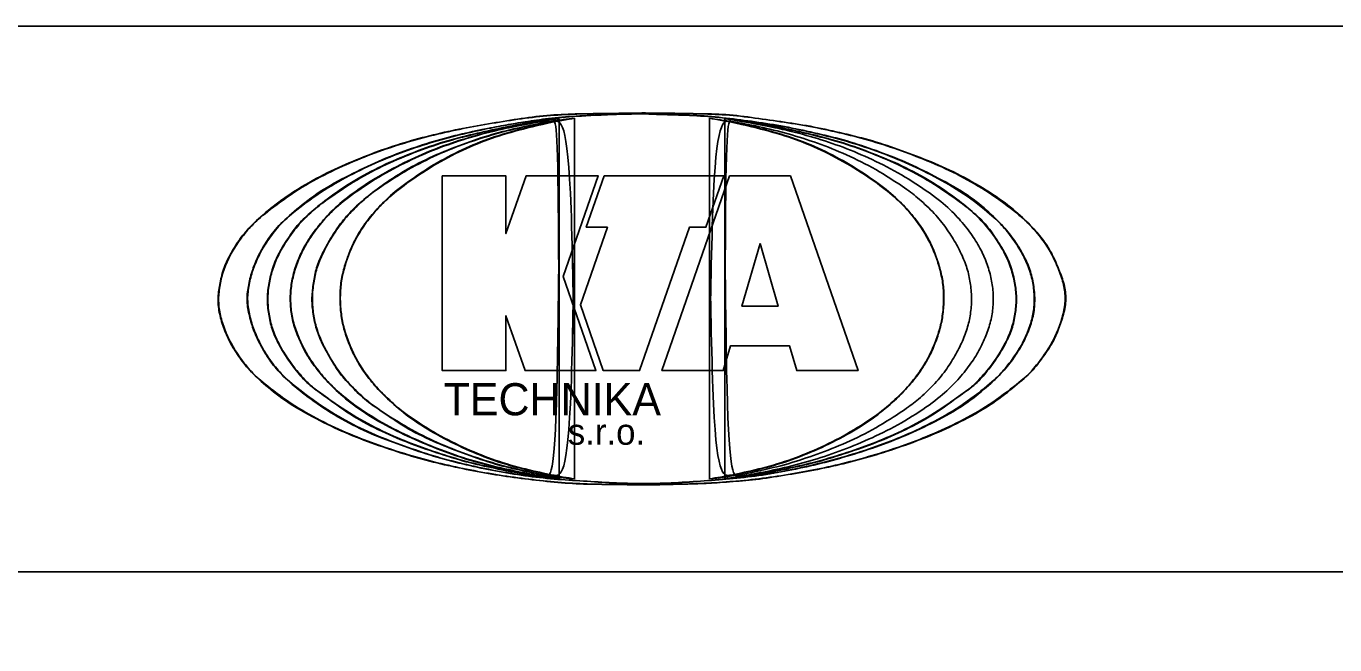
# Model space of a CAD drawing. Extents: x 25 to 46, y -50 to -20.3.
# Drawn here: x 37.705 to 42.505, y -37.068 to -34.8 of the extents above; entities that cross this region are included whole.
import ezdxf

# ---------------------------------------------------------------- set-up
doc = ezdxf.new("R2010")
doc.units = 0
doc.layers.add('_popis', color=7, linetype='Continuous')
doc.layers.add('Rozpiska_pole_6', color=7, linetype='Continuous')

msp = doc.modelspace()

# ---------------------------------------------------------------- linework, layer by layer
at = {"layer": '_popis'}
for p, q in [((40.2681, -35.1392), (40.2677, -36.458)), ((39.2313, -35.3488), (39.2313, -36.0628)), ((39.465, -35.3488), (39.2313, -35.3488)), ((39.5386, -35.3488), (39.465, -35.5605)), ((39.465, -35.5605), (39.465, -35.3488)), ((39.8036, -35.3488), (39.5386, -35.3488)), ((39.675, -35.7182), (39.8036, -35.3488)), ((39.825, -35.3488), (39.7594, -35.5375)), ((40.2641, -35.3488), (39.825, -35.3488)), ((40.037, -36.0626), (40.2855, -35.3488)), ((40.1984, -35.5375), (40.2641, -35.3488)), ((40.2855, -35.3488), (40.3969, -35.3488)), ((40.3969, -35.3488), (40.5083, -35.3488)), ((40.5083, -35.3488), (40.7567, -36.0626)), ((39.8369, -35.5375), (39.7381, -35.8213)), ((39.7594, -35.5375), (39.8369, -35.5375)), ((39.9551, -36.0628), (40.1379, -35.5375)), ((40.1379, -35.5375), (40.1984, -35.5375)), ((40.3969, -35.5973), (40.3305, -35.8269)), ((40.4633, -35.8269), (40.3969, -35.5973)), ((39.795, -36.0628), (39.675, -35.7182)), ((39.7381, -35.8213), (39.8222, -36.0628)), ((40.3305, -35.8269), (40.3969, -35.8269)), ((40.3969, -35.8269), (40.4633, -35.8269)), ((39.465, -36.0628), (39.465, -35.8616)), ((39.465, -35.8616), (39.535, -36.0628)), ((40.2887, -35.9716), (40.2623, -36.0628)), ((40.3969, -35.9716), (40.2887, -35.9716)), ((40.5051, -35.9716), (40.3969, -35.9716)), ((40.5315, -36.0628), (40.5051, -35.9716)), ((39.2313, -36.0628), (39.465, -36.0628)), ((39.535, -36.0628), (39.795, -36.0628)), ((39.8222, -36.0628), (39.9551, -36.0628)), ((40.2623, -36.0628), (40.037, -36.0626)), ((40.7567, -36.0626), (40.5315, -36.0628))]:
    msp.add_line(p, q, dxfattribs=at)
for points in [[(39.2313, -35.3488), (39.2313, -36.0628), (39.465, -36.0628), (39.465, -35.8616), (39.535, -36.0628), (39.795, -36.0628), (39.675, -35.7182), (39.8036, -35.3488), (39.5386, -35.3488), (39.465, -35.5605), (39.465, -35.3488), (39.2313, -35.3488)], [(39.825, -35.3488), (39.7594, -35.5375), (39.8369, -35.5375), (39.7381, -35.8213), (39.8222, -36.0628), (39.9551, -36.0628), (40.1379, -35.5375), (40.1984, -35.5375), (40.2641, -35.3488), (39.825, -35.3488)], [(40.3969, -35.9716), (40.2887, -35.9716), (40.2623, -36.0628), (40.037, -36.0626), (40.2855, -35.3488), (40.3969, -35.3488)], [(40.3969, -35.9716), (40.5051, -35.9716), (40.5315, -36.0628), (40.7567, -36.0626), (40.5083, -35.3488), (40.3969, -35.3488)], [(40.3969, -35.8269), (40.3305, -35.8269), (40.3969, -35.5973)], [(40.3969, -35.8269), (40.4633, -35.8269), (40.3969, -35.5973)]]:
    msp.add_lwpolyline(points, dxfattribs=at)
for points, degree in [([(39.9639, -35.1182), (39.9235, -35.1188), (39.852, -35.1199), (39.7448, -35.1208), (39.642, -35.1242), (39.5347, -35.1357), (39.4277, -35.1537), (39.3201, -35.1713), (39.2128, -35.1946), (39.1051, -35.2223), (38.9975, -35.2573), (38.8906, -35.3005), (38.7817, -35.3493), (38.6736, -35.4136), (38.589, -35.4768), (38.5246, -35.5353), (38.4849, -35.5846), (38.452, -35.639), (38.4265, -35.6924), (38.4148, -35.7474), (38.4067, -35.8011), (38.4133, -35.8559), (38.4303, -35.9096), (38.4542, -35.9643), (38.4893, -36.0177), (38.5268, -36.0666), (38.5904, -36.1238), (38.6724, -36.1873), (38.7823, -36.2472), (38.8896, -36.2978), (38.9979, -36.3377), (39.1054, -36.3729), (39.2125, -36.4023), (39.3197, -36.4256), (39.427, -36.4454), (39.5348, -36.4603), (39.6419, -36.4721), (39.7493, -36.4805), (39.8565, -36.4792), (39.9639, -36.483), (40.0712, -36.4798), (40.1532, -36.4786), (40.1993, -36.4763), (40.2097, -36.4757)], 3), ([(39.9639, -35.1182), (39.8427, -35.1199), (39.7495, -35.1211), (39.6423, -35.1255), (39.5351, -35.1368), (39.4279, -35.1536), (39.3205, -35.1722), (39.2133, -35.1952), (39.1061, -35.2232), (38.9987, -35.2583), (38.8915, -35.3009), (38.7849, -35.3503), (38.6775, -35.4138), (38.5703, -35.4945), (38.5286, -35.5334), (38.4849, -35.5873), (38.4523, -35.6406), (38.4282, -35.6944), (38.4153, -35.7478), (38.4091, -35.8015), (38.4147, -35.8543), (38.431, -35.9085), (38.4551, -35.9623), (38.4888, -36.0156), (38.532, -36.0694), (38.5702, -36.1052), (38.6774, -36.1865), (38.7846, -36.2471), (38.8906, -36.2964), (38.9989, -36.3373), (39.1065, -36.3723), (39.2131, -36.4014), (39.3197, -36.425), (39.4275, -36.4446), (39.535, -36.4598), (39.6427, -36.4716), (39.7487, -36.4789), (39.8568, -36.4801), (39.9639, -36.4818), (40.0711, -36.4801), (40.1786, -36.4773), (40.2858, -36.4705), (40.3924, -36.4605), (40.4999, -36.4442), (40.6071, -36.4251), (40.7143, -36.401), (40.8218, -36.3713), (40.929, -36.336), (41.0362, -36.2945), (41.1428, -36.2446), (41.2508, -36.1813), (41.3585, -36.0978), (41.3905, -36.0692), (41.4326, -36.0159), (41.468, -35.9626), (41.4928, -35.9085), (41.5102, -35.8552), (41.5187, -35.8015), (41.5124, -35.748), (41.4939, -35.6942), (41.4698, -35.6394), (41.4378, -35.5872), (41.3924, -35.5334), (41.3593, -35.5009), (41.2509, -35.417), (41.1437, -35.3537), (41.0373, -35.3029), (40.9295, -35.2614), (40.8218, -35.2244), (40.7152, -35.1964), (40.6071, -35.1722), (40.4994, -35.1537), (40.3917, -35.1386), (40.2853, -35.125), (40.1784, -35.1211), (40.0713, -35.1192), (39.9639, -35.1182), (39.9639, -35.1182), (39.9639, -35.1182)], 3), ([(39.9639, -35.1211), (39.9997, -35.1226), (40.0713, -35.1255), (40.1787, -35.1265), (40.2858, -35.1383), (40.393, -35.1519), (40.5005, -35.1698), (40.6076, -35.1935), (40.7158, -35.2191), (40.8227, -35.2556), (40.9309, -35.2969), (41.0378, -35.3497), (41.1493, -35.4096), (41.2316, -35.4752), (41.2925, -35.5363), (41.331, -35.5848), (41.364, -35.639), (41.3885, -35.6928), (41.4013, -35.7476), (41.406, -35.8017), (41.4019, -35.8563), (41.3856, -35.9101), (41.3615, -35.9642), (41.3273, -36.0178), (41.2909, -36.0655), (41.2291, -36.1234), (41.1493, -36.1893), (41.0386, -36.2517), (40.9304, -36.3018), (40.8228, -36.3436), (40.715, -36.3773), (40.6078, -36.4072), (40.5001, -36.4295), (40.393, -36.4491), (40.2855, -36.4596), (40.1784, -36.4688), (40.0713, -36.4757), (39.9639, -36.4792), (39.8566, -36.4751), (39.7494, -36.4675), (39.6419, -36.4616), (39.5346, -36.4489), (39.4272, -36.4315), (39.3199, -36.4087), (39.2119, -36.3821), (39.1053, -36.3453), (38.9969, -36.3064), (38.8884, -36.2571), (38.7805, -36.1918), (38.696, -36.1276), (38.6313, -36.0686), (38.5928, -36.0182), (38.5608, -35.9637), (38.5367, -35.9099), (38.5218, -35.8558), (38.5123, -35.8015), (38.5206, -35.7471), (38.5345, -35.693), (38.5572, -35.6389), (38.589, -35.5849), (38.6276, -35.5322), (38.6946, -35.4726), (38.7792, -35.4054), (38.8901, -35.3461), (38.997, -35.2943), (39.1048, -35.2523), (39.2124, -35.218), (39.32, -35.1904), (39.4116, -35.1723), (39.4832, -35.1591), (39.5546, -35.1477), (39.6419, -35.1348), (39.7494, -35.1281), (39.8567, -35.1236), (39.9282, -35.122), (39.9639, -35.1211)], 3), ([(39.9639, -35.1211), (39.8567, -35.124), (39.7495, -35.1284), (39.6423, -35.1363), (39.5351, -35.1509), (39.4869, -35.1587), (39.428, -35.1694), (39.3205, -35.1913), (39.2133, -35.2188), (39.1059, -35.2532), (38.9988, -35.2952), (38.8914, -35.3463), (38.7848, -35.4063), (38.6775, -35.4883), (38.6298, -35.5333), (38.5888, -35.5872), (38.558, -35.6404), (38.5355, -35.6944), (38.5215, -35.7477), (38.5153, -35.8015), (38.5226, -35.8551), (38.5377, -35.9083), (38.5613, -35.9622), (38.5928, -36.0158), (38.6349, -36.0696), (38.6775, -36.11), (38.7847, -36.1919), (38.8914, -36.256), (38.9986, -36.3054), (39.1058, -36.3452), (39.2132, -36.3807), (39.3204, -36.4082), (39.4276, -36.4306), (39.535, -36.4482), (39.6422, -36.4605), (39.7494, -36.4678), (39.8567, -36.4745), (39.9639, -36.4779), (40.0711, -36.4751), (40.1786, -36.4684), (40.2852, -36.4594), (40.3924, -36.4476), (40.4999, -36.4291), (40.607, -36.4061), (40.7142, -36.3769), (40.8217, -36.3426), (40.9289, -36.3011), (41.0361, -36.2512), (41.1435, -36.1886), (41.2507, -36.1028), (41.285, -36.0695), (41.3277, -36.0156), (41.3608, -35.9624), (41.3849, -35.9085), (41.4, -35.8553), (41.4045, -35.802), (41.4, -35.7479), (41.3871, -35.6947), (41.3636, -35.6408), (41.331, -35.5872), (41.2883, -35.5333), (41.2507, -35.4952), (41.1436, -35.4105), (41.0362, -35.3496), (40.929, -35.298), (40.8218, -35.256), (40.7144, -35.2206), (40.6073, -35.1937), (40.5001, -35.1707), (40.3926, -35.1526), (40.2855, -35.1385), (40.1786, -35.1283), (40.0714, -35.1249), (39.9639, -35.1211), (39.9639, -35.1211), (39.9639, -35.1211)], 3), ([(39.7161, -36.4596), (39.6914, -36.4575), (39.6304, -36.4523), (39.5347, -36.4318), (39.4265, -36.4074), (39.3198, -36.3704), (39.2116, -36.3288), (39.1018, -36.2769), (39.021, -36.2196), (38.9493, -36.1723), (38.9019, -36.1253), (38.8532, -36.0728), (38.8201, -36.0165), (38.7893, -35.964), (38.7686, -35.9101), (38.7572, -35.8559), (38.7513, -35.8017), (38.7578, -35.7476), (38.7662, -35.6929), (38.7884, -35.6393), (38.817, -35.5858), (38.8518, -35.5308), (38.8972, -35.476), (38.9485, -35.4304), (39.0183, -35.3777), (39.1027, -35.3224), (39.2113, -35.2692), (39.3191, -35.2272), (39.4263, -35.1919), (39.5343, -35.1674), (39.6305, -35.1475), (39.6915, -35.1406), (39.7161, -35.1377)], 3), ([(39.7161, -36.4596), (39.6424, -36.452), (39.5346, -36.4316), (39.4284, -36.4058), (39.3206, -36.3701), (39.2131, -36.3279), (39.1064, -36.2754), (38.9989, -36.2052), (38.9585, -36.1768), (38.9001, -36.1227), (38.8538, -36.0696), (38.8196, -36.0157), (38.7902, -35.9621), (38.7697, -35.9085), (38.7581, -35.856), (38.7533, -35.8017), (38.7581, -35.7475), (38.7681, -35.6945), (38.7886, -35.6412), (38.8175, -35.5866), (38.8517, -35.5335), (38.8964, -35.4796), (38.9552, -35.426), (38.9994, -35.3924), (39.1063, -35.3233), (39.213, -35.2702), (39.3208, -35.2277), (39.4272, -35.1935), (39.5345, -35.1677), (39.6424, -35.1471), (39.7161, -35.1377), (39.7161, -36.4596), (39.7161, -35.1377)], 3), ([(39.7161, -35.1377), (39.6915, -35.1413), (39.6306, -35.1502), (39.5345, -35.1738), (39.426, -35.2027), (39.3179, -35.2449), (39.2101, -35.3004), (39.1156, -35.3622), (39.0382, -35.4217), (38.9841, -35.4775), (38.9415, -35.531), (38.9092, -35.5853), (38.8859, -35.6396), (38.8686, -35.6935), (38.8574, -35.7474), (38.8558, -35.8015), (38.8589, -35.8555), (38.8693, -35.9097), (38.8885, -35.9631), (38.9121, -36.0178), (38.946, -36.0711), (38.9886, -36.1254), (39.0426, -36.1786), (39.1162, -36.2399), (39.21, -36.2985), (39.3183, -36.352), (39.4258, -36.3958), (39.5342, -36.4259), (39.631, -36.446), (39.6914, -36.4557), (39.7161, -36.4596)], 3), ([(39.7161, -35.1377), (39.6424, -35.1494), (39.5353, -35.174), (39.4276, -35.2044), (39.3205, -35.2459), (39.2132, -35.3011), (39.1061, -35.3706), (39.0357, -35.4266), (38.9836, -35.4798), (38.9415, -35.5336), (38.9099, -35.5869), (38.8865, -35.6407), (38.8694, -35.6943), (38.8589, -35.7481), (38.8565, -35.8013), (38.86, -35.8551), (38.8706, -35.9089), (38.8887, -35.9621), (38.9128, -36.0157), (38.9461, -36.0695), (38.9877, -36.1221), (39.0416, -36.1762), (39.106, -36.2294), (39.213, -36.2978), (39.3203, -36.3513), (39.4274, -36.394), (39.5356, -36.425), (39.6423, -36.4473), (39.7161, -36.4596), (39.7161, -35.1377), (39.7161, -36.4596)], 3), ([(40.2097, -36.4757), (40.235, -36.4743), (40.296, -36.4699), (40.3931, -36.4618), (40.5, -36.4443), (40.6076, -36.426), (40.715, -36.4017), (40.8225, -36.3721), (40.93, -36.3366), (41.0376, -36.2954), (41.1457, -36.2449), (41.256, -36.1823), (41.3346, -36.1179), (41.398, -36.0648), (41.4318, -36.0169), (41.4691, -35.965), (41.4932, -35.9098), (41.5113, -35.8562), (41.5216, -35.8018), (41.5143, -35.7463), (41.4938, -35.6932), (41.471, -35.6383), (41.4374, -35.5837), (41.3984, -35.5387), (41.3381, -35.4793), (41.2557, -35.4172), (41.1464, -35.3533), (41.0387, -35.3015), (40.9301, -35.2615), (40.8235, -35.2229), (40.7151, -35.1961), (40.6078, -35.1712), (40.4996, -35.1531), (40.3922, -35.1391), (40.2856, -35.1225), (40.1783, -35.1213), (40.0712, -35.119), (39.9997, -35.1184), (39.9639, -35.1182)], 3), ([(40.2117, -35.1377), (40.2364, -35.1413), (40.2973, -35.1502), (40.3933, -35.1738), (40.5018, -35.2027), (40.6099, -35.2449), (40.7178, -35.3004), (40.8123, -35.3622), (40.8896, -35.4217), (40.9437, -35.4775), (40.9863, -35.531), (41.0186, -35.5853), (41.0419, -35.6396), (41.0592, -35.6935), (41.0705, -35.7474), (41.0721, -35.8015), (41.069, -35.8555), (41.0585, -35.9097), (41.0394, -35.9631), (41.0158, -36.0178), (40.9819, -36.0711), (40.9392, -36.1254), (40.8852, -36.1786), (40.8116, -36.2399), (40.7178, -36.2985), (40.6095, -36.352), (40.502, -36.3958), (40.3936, -36.4259), (40.2969, -36.446), (40.2364, -36.4557), (40.2118, -36.4596)], 3), ([(40.2117, -35.1377), (40.2855, -35.1494), (40.3926, -35.174), (40.5002, -35.2044), (40.6073, -35.2459), (40.7146, -35.3011), (40.8217, -35.3706), (40.8921, -35.4266), (40.9442, -35.4798), (40.9863, -35.5336), (41.0179, -35.5869), (41.0413, -35.6407), (41.0584, -35.6943), (41.069, -35.7481), (41.0713, -35.8013), (41.0678, -35.8551), (41.0573, -35.9089), (41.0391, -35.9621), (41.0151, -36.0157), (40.9817, -36.0695), (40.9402, -36.1221), (40.8863, -36.1762), (40.8219, -36.2294), (40.7148, -36.2978), (40.6075, -36.3513), (40.5005, -36.394), (40.3922, -36.425), (40.2855, -36.4473), (40.2118, -36.4596), (40.2117, -35.1377), (40.2118, -36.4596)], 3), ([(40.2118, -36.4596), (40.2855, -36.452), (40.3932, -36.4316), (40.4994, -36.4058), (40.6072, -36.3701), (40.7147, -36.3279), (40.8214, -36.2754), (40.9289, -36.2052), (40.9694, -36.1768), (41.0277, -36.1227), (41.074, -36.0696), (41.1082, -36.0157), (41.1376, -35.9621), (41.1581, -35.9085), (41.1697, -35.856), (41.1745, -35.8017), (41.1698, -35.7475), (41.1598, -35.6945), (41.1393, -35.6412), (41.1104, -35.5866), (41.0762, -35.5335), (41.0315, -35.4796), (40.9726, -35.426), (40.9284, -35.3924), (40.8216, -35.3233), (40.7149, -35.2702), (40.6071, -35.2277), (40.5006, -35.1935), (40.3934, -35.1677), (40.2854, -35.1471), (40.2117, -35.1377), (40.2118, -36.4596), (40.2117, -35.1377)], 3), ([(39.6602, -36.458), (39.6397, -36.4563), (39.5976, -36.4528), (39.5198, -36.4409), (39.4269, -36.4217), (39.3184, -36.3987), (39.2116, -36.3644), (39.1038, -36.3273), (38.9959, -36.2806), (38.8864, -36.2219), (38.8103, -36.1619), (38.7425, -36.1172), (38.7024, -36.072), (38.6615, -36.0175), (38.6297, -35.9637), (38.605, -35.9105), (38.5941, -35.8555), (38.5881, -35.8016), (38.5939, -35.7473), (38.6063, -35.6931), (38.6272, -35.6379), (38.6605, -35.5856), (38.6988, -35.5289), (38.7427, -35.4867), (38.8068, -35.4345), (38.8874, -35.3779), (38.9961, -35.3167), (39.1047, -35.2712), (39.2116, -35.2305), (39.3197, -35.2014), (39.4279, -35.1771), (39.5349, -35.1558), (39.6124, -35.142), (39.6542, -35.1395), (39.6598, -35.1392)], 3), ([(39.6602, -36.458), (39.5987, -36.4522), (39.5345, -36.4427), (39.4273, -36.4217), (39.3195, -36.397), (39.212, -36.3641), (39.1053, -36.3263), (38.9986, -36.2801), (38.891, -36.2205), (38.7832, -36.1443), (38.7543, -36.1238), (38.7017, -36.0697), (38.6611, -36.0148), (38.6301, -35.9622), (38.6069, -35.9092), (38.5948, -35.8548), (38.59, -35.8012), (38.5948, -35.7486), (38.6074, -35.694), (38.6284, -35.64), (38.66, -35.587), (38.6984, -35.5334), (38.753, -35.4787), (38.7825, -35.4546), (38.891, -35.3782), (38.9993, -35.3178), (39.1062, -35.2713), (39.2118, -35.2324), (39.3215, -35.2018), (39.4277, -35.1776), (39.5355, -35.1561), (39.643, -35.1403), (39.6598, -35.1392), (39.6602, -36.458), (39.6598, -35.1392)], 3), ([(39.6598, -35.1392), (39.6211, -35.145), (39.5434, -35.1566), (39.4299, -35.18), (39.3193, -35.2104), (39.2112, -35.2461), (39.1041, -35.2935), (38.9959, -35.3501), (38.9011, -35.412), (38.8266, -35.4743), (38.7771, -35.5313), (38.7382, -35.5846), (38.7093, -35.6388), (38.6886, -35.693), (38.6762, -35.7474), (38.6726, -35.8018), (38.6765, -35.8558), (38.6901, -35.9101), (38.7131, -35.9634), (38.7413, -36.0185), (38.7818, -36.0714), (38.8307, -36.127), (38.9025, -36.1891), (38.9959, -36.2499), (39.1046, -36.3045), (39.2124, -36.3503), (39.3194, -36.3886), (39.4271, -36.4174), (39.5243, -36.4371), (39.6021, -36.4501), (39.6439, -36.4558), (39.6602, -36.458)], 3), ([(39.6598, -35.1392), (39.5441, -35.1576), (39.4279, -35.1817), (39.3201, -35.2112), (39.2125, -35.2476), (39.1063, -35.2938), (38.9991, -35.3506), (38.8916, -35.4218), (38.8243, -35.4796), (38.7764, -35.5337), (38.7386, -35.5868), (38.7102, -35.6399), (38.6896, -35.6943), (38.6775, -35.7484), (38.6738, -35.8014), (38.678, -35.8554), (38.6912, -35.9085), (38.7133, -35.9621), (38.7422, -36.0162), (38.7811, -36.0693), (38.829, -36.1228), (38.8926, -36.1785), (38.9988, -36.2489), (39.1066, -36.3041), (39.2136, -36.3496), (39.3208, -36.3874), (39.4276, -36.4163), (39.5351, -36.4385), (39.6113, -36.4511), (39.6602, -36.458), (39.6598, -35.1392), (39.6602, -36.458)], 3), ([(40.2677, -36.458), (40.2882, -36.4563), (40.3303, -36.4528), (40.408, -36.4409), (40.501, -36.4217), (40.6094, -36.3987), (40.7162, -36.3644), (40.824, -36.3273), (40.9319, -36.2806), (41.0414, -36.2219), (41.1176, -36.1619), (41.1853, -36.1172), (41.2255, -36.072), (41.2664, -36.0175), (41.2981, -35.9637), (41.3228, -35.9105), (41.3338, -35.8555), (41.3397, -35.8016), (41.334, -35.7473), (41.3216, -35.6931), (41.3007, -35.6379), (41.2673, -35.5856), (41.229, -35.5289), (41.1851, -35.4867), (41.1211, -35.4345), (41.0404, -35.3779), (40.9318, -35.3167), (40.8231, -35.2712), (40.7162, -35.2305), (40.6081, -35.2014), (40.4999, -35.1771), (40.3929, -35.1558), (40.3154, -35.142), (40.2737, -35.1395), (40.2681, -35.1392)], 3), ([(40.2677, -36.458), (40.3292, -36.4522), (40.3933, -36.4427), (40.5006, -36.4217), (40.6083, -36.397), (40.7158, -36.3641), (40.8225, -36.3263), (40.9293, -36.2801), (41.0368, -36.2205), (41.1446, -36.1443), (41.1735, -36.1238), (41.2261, -36.0697), (41.2667, -36.0148), (41.2978, -35.9622), (41.3209, -35.9092), (41.3331, -35.8548), (41.3378, -35.8012), (41.3331, -35.7486), (41.3205, -35.694), (41.2994, -35.64), (41.2679, -35.587), (41.2295, -35.5334), (41.1748, -35.4787), (41.1454, -35.4546), (41.0368, -35.3782), (40.9285, -35.3178), (40.8217, -35.2713), (40.716, -35.2324), (40.6063, -35.2018), (40.5001, -35.1776), (40.3924, -35.1561), (40.2849, -35.1403), (40.2681, -35.1392), (40.2677, -36.458), (40.2681, -35.1392)], 3), ([(40.2681, -35.1392), (40.3837, -35.1576), (40.4999, -35.1817), (40.6077, -35.2112), (40.7153, -35.2476), (40.8215, -35.2938), (40.9288, -35.3506), (41.0363, -35.4218), (41.1036, -35.4796), (41.1514, -35.5337), (41.1893, -35.5868), (41.2177, -35.6399), (41.2382, -35.6943), (41.2503, -35.7484), (41.254, -35.8014), (41.2498, -35.8554), (41.2367, -35.9085), (41.2146, -35.9621), (41.1857, -36.0162), (41.1468, -36.0693), (41.0988, -36.1228), (41.0352, -36.1785), (40.929, -36.2489), (40.8213, -36.3041), (40.7142, -36.3496), (40.607, -36.3874), (40.5003, -36.4163), (40.3928, -36.4385), (40.3165, -36.4511), (40.2677, -36.458), (40.2681, -35.1392), (40.2677, -36.458)], 3), ([(40.2118, -36.4596), (40.2118, -36.4596), (40.2118, -36.4596), (40.2118, -36.4596)], 2), ([(40.2677, -36.458), (40.2677, -36.458), (40.2677, -36.458), (40.2677, -36.458)], 2)]:
    msp.add_open_spline(points, degree=degree, dxfattribs=at)
at = {"layer": 'Rozpiska_pole_6'}
msp.add_line((27, -36.8), (44, -36.8), dxfattribs=at)
msp.add_lwpolyline([(27, -34.8), (44, -34.8), (44, -39.8), (27, -39.8)], close=True, dxfattribs=at)

# ---------------------------------------------------------------- texts
at = {"layer": '_popis'}
for s, height, p in [('TECHNIKA', 0.11795, (39.2362, -36.2268)), ('s.r.o.', 0.09543, (39.6919, -36.3347))]:
    msp.add_text(s, height=height, dxfattribs=at).set_placement(p)

doc.saveas('drawing.dxf')
